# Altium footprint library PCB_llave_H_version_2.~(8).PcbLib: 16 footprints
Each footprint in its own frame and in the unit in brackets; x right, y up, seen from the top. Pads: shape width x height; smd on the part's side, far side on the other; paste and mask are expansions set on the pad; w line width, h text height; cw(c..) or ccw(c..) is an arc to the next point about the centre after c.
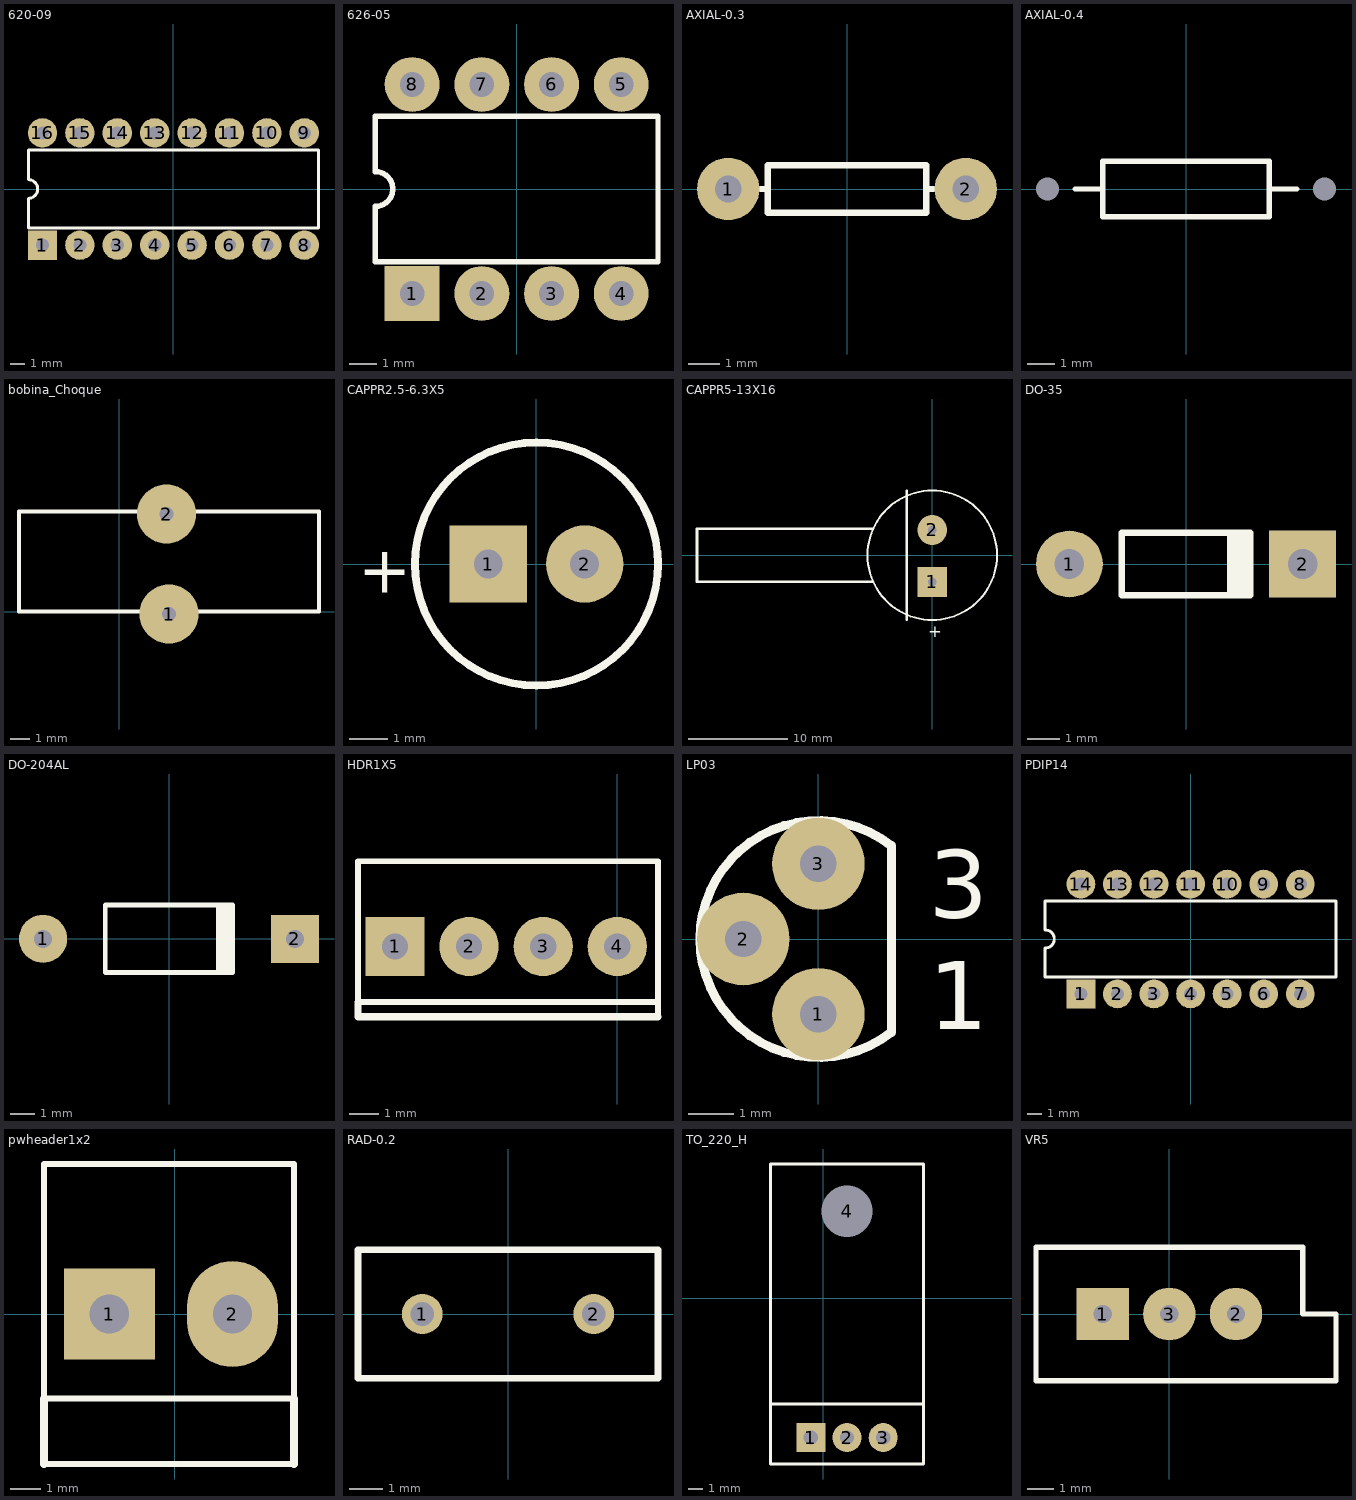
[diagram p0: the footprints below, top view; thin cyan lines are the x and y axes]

## 620-09 [mm] "DIP; 16 Leads; Row Spacing 7.62 mm; Pitch 2.54 mm"
height 4.19
pads (16):
  rect 2x2 hole 0.9: 1(-8.89,-3.81)
  round 2 hole 0.9: 2(-6.35,-3.81) 3(-3.81,-3.81) 4(-1.27,-3.81) 5(1.27,-3.81) 6(3.81,-3.81) 7(6.35,-3.81) 8(8.89,-3.81) 9(8.89,3.81) 10(6.35,3.81) 11(3.81,3.81) 12(1.27,3.81) 13(-1.27,3.81) 14(-3.81,3.81) 15(-6.35,3.81) 16(-8.89,3.81)
Top Overlay:
  lines w0.2: -9.85,-2.65 -9.85,-0.635 ccw(c-9.85,0) -9.85,0.635 -9.85,2.65 9.85,2.65 9.85,-2.65 -9.85,-2.65

## 626-05 [mm] "DIP; 8 Leads; Row Spacing 7.62 mm; Pitch 2.54 mm"
height 4.45
pads (8):
  rect 2x2 hole 0.9: 1(-3.81,-3.81)
  round 2 hole 0.9: 2(-1.27,-3.81) 3(1.27,-3.81) 4(3.81,-3.81) 5(3.81,3.81) 6(1.27,3.81) 7(-1.27,3.81) 8(-3.81,3.81)
Top Overlay:
  lines w0.2: -5.15,-2.65 5.15,-2.65 5.15,2.65 -5.15,2.65 -5.15,0.635 cw(c-5.15,0) -5.15,-0.635 -5.15,-2.65

## AXIAL-0.3 [mm] "Resistor; 2 Leads"
height 1.524
pads (2):
  round 2 hole 0.85: 1(-3.81,0) 2(3.81,0)
Top Overlay:
  lines w0.2: -2.769,0 -2.54,0 ; 2.769,0 2.54,0 ; 2.54,0 2.54,0.762 -2.54,0.762 -2.54,-0.762 2.54,-0.762 2.54,0

## AXIAL-0.4 [mm] "Resistor; 2 Leads"
height 2.032
pads (2):
  round 0 / inner round 0 / far side round 2 hole 0.85: 1(-5.08,0) 2(5.08,0)
Top Overlay:
  lines w0.2: -4.064,0 -3.048,0 ; 3.048,0 4.064,0 ; -3.048,-1.016 3.048,-1.016 3.048,1.016 -3.048,1.016 -3.048,-1.016

## bobina_Choque [mm]
pads (2):
  round 3 hole 0.7: 1(2.54,-0.127) 2(2.413,4.953)
Top Overlay:
  lines w0.2: -5.08,0 10.16,0 10.16,5.08 -5.08,5.08 -5.08,0

## CAPPR2.5-6.3X5 [mm] "Capacitor, Electrolytic, Radial; Body 6.3 x 5 mm (Dia.xH typ); Pin Spacing 2.5 mm (typ)"
height 6
pads (2):
  rect 2x2 hole 0.75: 1(-1.25,0)
  round 2 hole 0.75: 2(1.25,0)
Top Overlay:
  circle w0.2: c0,0 r3.15
  text "+" at -4.625,-0.75 h1.2

## CAPPR5-13X16 [mm] "Capacitor, Electrolytic, Radial; Body 13 x 16 mm (Dia.xH typ); Pin Spacing 5 mm (typ)"
height 18
pads (2):
  rect 3x3 hole 0.9: 1(0,-2.667)
  round 3 hole 0.9: 2(0,2.54)
Top Overlay:
  circle w0.2: c0,0 r6.5
  lines w0.254: -23.622,2.54 -23.622,-2.667 -5.969,-2.667 ; -23.622,2.667 -5.969,2.667 ; -2.54,-6.477 -2.54,6.477
  text "+" at -0.381,-8.255 h1.2

## DO-35 [mil] "Diode, Axial; Body 3.8 x 1.9 mm (LxDia. max), Lead Dia. 0.53 mm (max)"
height 74.8
pads (2):
  round 80 hole 35.43: 1(-139.76,0)
  rect 80x80 hole 35.43: 2(139.76,0)
Top Overlay:
  rectangle: 49.21,-37.4 80.71,37.4
  lines w7.87: 76.77,-37.4 -76.77,-37.4 -76.77,37.4 76.77,37.4

## DO-204AL [mm] "Diode, Axial; Body 5.2 x 2.7 mm (LxDia. max), Lead Dia. 0.86 mm (max)"
height 2.7
pads (2):
  round 2 hole 0.75: 1(-5.23,0)
  rect 2x2 hole 0.75: 2(5.23,0)
Top Overlay:
  rectangle: 1.95,-1.413 2.75,1.387
  lines w0.2: 2.65,-1.4 -2.65,-1.4 -2.65,1.4 2.65,1.4

## HDR1X5 [mil]
pads (4):
  rect 80x80 hole 35.43: 1(-300,300)
  round 80 / inner round 0 / far side round 80 hole 35.43: 2(-200,300) 3(-100,300) 4(0,300)
Top Overlay:
  lines w7.87: 55,205 55,415 -350,415 -350,225 55,225
  lines w10: -350,225 -350,205 55,205

## LP03 [mil] "TO, Flat Index; 3 In-Line, Axial Leads; Body Dia. 4.8mm; Leads 0.56 x 0.41 mm (max)"
height 210.24
pads (3):
  round 80 hole 31.5: 1(0,-65) 2(-65,0) 3(0,65)
Top Overlay:
  lines w7.87: 63.02,-80.66 cw(c0,0) 63.02,80.66 ; 62.99,-78.35 62.99,78.35
  text "1" at 95.31,-77.91 h59.05
  text "3" at 95.31,18.39 h59.05

## PDIP14 [mm] "DIP; 14 Leads; Row Spacing 7.62 mm; Pitch 2.54 mm"
height 5.33
pads (14):
  rect 2x2 hole 0.9: 1(-7.62,-3.81)
  round 2 hole 0.9: 2(-5.08,-3.81) 3(-2.54,-3.81) 4(0,-3.81) 5(2.54,-3.81) 6(5.08,-3.81) 7(7.62,-3.81) 8(7.62,3.81) 9(5.08,3.81) 10(2.54,3.81) 11(0,3.81) 12(-2.54,3.81) 13(-5.08,3.81) 14(-7.62,3.81)
Top Overlay:
  lines w0.2: -10.1,-2.65 -10.1,-0.635 ccw(c-10.1,0) -10.1,0.635 -10.1,2.65 10.1,2.65 10.1,-2.65 -10.1,-2.65

## pwheader1x2 [mm]
pads (2):
  rect 3x3 / inner round 0 / far side rect 3x3.5 hole 1.3: 1(-2.159,0)
  oval 3x3.5 / inner round 0 / far side oval 3x3.5 hole 1.3: 2(1.905,0)
Top Overlay:
  lines w0.2: -4.318,-4.953 3.937,-4.953 ; -4.318,-2.794 -4.318,4.953 3.937,4.953 3.937,-2.794 -4.318,-2.794
  lines w0.254: -4.318,-4.953 -4.318,-2.794 ; 3.937,-4.953 3.937,-2.794

## RAD-0.2 [mm] "Jumper Wire; 2 Leads"
pads (2):
  round 1.2 hole 0.7: 1(-2.54,0) 2(2.54,0)
Top Overlay:
  lines w0.2: -4.445,-1.905 4.445,-1.905 4.445,1.905 -4.445,1.905 -4.445,-1.905

## TO_220_H [mil] "to-220 horizontal"
pads (4):
  rect 80x80 hole 39.37: 1(-35,-385)
  round 80 hole 39.37: 2(65,-385) 3(165,-385)
  round 80 hole 141.73: 4(65,240)
Top Overlay:
  lines w7.87: -145.63,-292.48 275.63,-292.48 ; -145.63,-457.83 -145.63,370 275.63,370 275.63,-457.83 -145.63,-457.83

## VR5 [mm] "Potentiometer; 3 Leads"
pads (3):
  rect 2x2 hole 0.7: 1(-2.54,0)
  round 2 hole 0.7: 2(2.54,0) 3(0,0)
Top Overlay:
  lines w0.2: -5.08,-2.54 6.35,-2.54 6.35,0 5.08,0 5.08,2.54 -5.08,2.54 -5.08,-2.54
